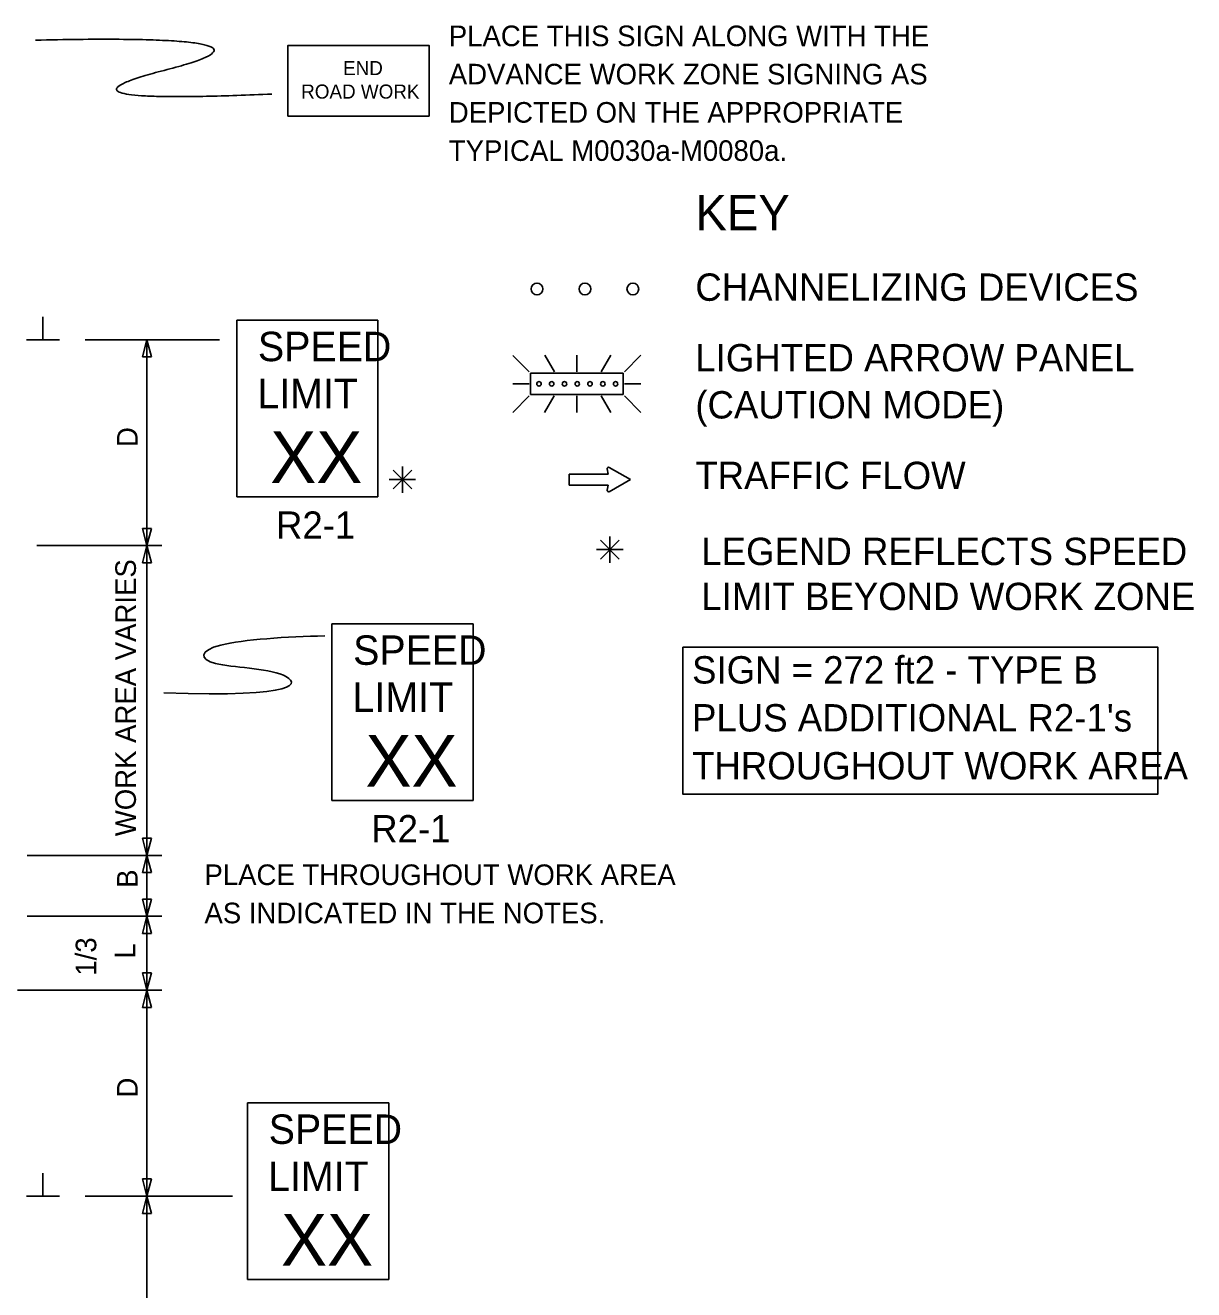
# Model space of a CAD drawing. Extents: x 16741 to 18479, y 6916 to 8211.
# Drawn here: x 17027.6 to 17424.7, y 7781.4 to 8211.2 of the extents above; entities that cross this region are included whole.
import ezdxf

# ---------------------------------------------------------------- set-up
doc = ezdxf.new("R2010")
doc.units = 0
for name, color, linetype in [('MT_SCRATCH_LEVEL_E', 7, 'Continuous'), ('PAVT_EDGE_EX', 7, 'Continuous'), ('TRAFFIC_SIGNS_PR', 7, 'Continuous'), ('TYPICAL_TEXT_DIMEN_EX', 7, 'Continuous'), ('TYPICAL_TEXT_DIMEN_PR', 7, 'Continuous')]:
    doc.layers.add(name, color=color, linetype=linetype)

msp = doc.modelspace()

# ---------------------------------------------------------------- linework, layer by layer
at = {"layer": 'MT_SCRATCH_LEVEL_E'}
for p, q in [((17225.35, 8060.43), (17225.67, 8058.65)), ((17225.35, 8060.43), (17225.67, 8058.65)), ((17233.28, 8056.8), (17226.04, 8060.91)), ((17233.28, 8056.8), (17226.04, 8060.91)), ((17225.67, 8058.65), (17212.41, 8058.65)), ((17212.41, 8058.65), (17212.41, 8054.91)), ((17225.67, 8058.65), (17212.41, 8058.65)), ((17212.41, 8058.65), (17212.41, 8054.91)), ((17212.41, 8054.91), (17225.67, 8054.91)), ((17212.41, 8054.91), (17225.67, 8054.91)), ((17225.67, 8054.91), (17225.35, 8053.13)), ((17225.67, 8054.91), (17225.35, 8053.13)), ((17226.04, 8052.65), (17233.28, 8056.8)), ((17226.04, 8052.65), (17233.28, 8056.8))]:
    msp.add_line(p, q, dxfattribs=at)
for centre, start, end in [((17225.81, 8060.5), 60.4248, 189.9638), ((17225.81, 8060.5), 60.4248, 189.9638), ((17225.81, 8053.06), 170.0362, 299.7731), ((17225.81, 8053.06), 170.0362, 299.7731)]:
    msp.add_arc(centre, 0.463, start, end, dxfattribs=at)
at = {"layer": 'PAVT_EDGE_EX'}
msp.add_line((17028.22, 7883.18), (17024.92, 7883.18), dxfattribs=at)
at = {"layer": 'TRAFFIC_SIGNS_PR'}
for p, q in [((17099.42, 8110.93), (17147.42, 8110.93)), ((17099.42, 8050.93), (17099.42, 8110.93)), ((17147.42, 8050.93), (17147.42, 8110.93)), ((17193.23, 8098.99), (17198.86, 8093.36)), ((17207.4, 8093.36), (17204.15, 8099)), ((17215.03, 8093.36), (17215.03, 8099)), ((17223.3, 8093.36), (17226.56, 8099)), ((17231.2, 8093.36), (17236.85, 8099)), ((17198.86, 8089.29), (17193.23, 8089.29)), ((17202.14, 8089.29), (17202.14, 8089.29)), ((17206.49, 8089.29), (17206.49, 8089.29)), ((17210.83, 8089.29), (17210.83, 8089.29)), ((17215.18, 8089.29), (17215.18, 8089.29)), ((17219.53, 8089.29), (17219.53, 8089.29)), ((17223.88, 8089.29), (17223.88, 8089.29)), ((17228.22, 8089.29), (17228.22, 8089.29)), ((17231.2, 8089.29), (17236.85, 8089.29)), ((17193.23, 8079.59), (17198.86, 8085.23)), ((17204.1, 8079.59), (17207.35, 8085.23)), ((17215.03, 8085.23), (17215.03, 8079.59)), ((17226.61, 8079.59), (17223.35, 8085.23)), ((17231.2, 8085.23), (17236.85, 8079.59)), ((17099.42, 8050.93), (17147.42, 8050.93)), ((17131.79, 8007.71), (17179.79, 8007.71)), ((17131.79, 7947.71), (17131.79, 8007.71)), ((17179.79, 7947.71), (17179.79, 8007.71)), ((17131.79, 7947.71), (17179.79, 7947.71)), ((17103.1, 7844.86), (17151.1, 7844.86)), ((17103.1, 7784.86), (17103.1, 7844.86)), ((17151.1, 7784.86), (17151.1, 7844.86)), ((17103.1, 7784.86), (17151.1, 7784.86))]:
    msp.add_line(p, q, dxfattribs=at)
for points in [[(17116.83, 8180.34), (17164.83, 8180.34), (17164.83, 8204.34), (17116.83, 8204.34)], [(17230.74, 8085.69), (17199.33, 8085.69), (17199.33, 8092.89), (17230.74, 8092.89)]]:
    msp.add_lwpolyline(points, close=True, dxfattribs=at)
for centre, radius in [((17201.49, 8121.55), 2), ((17217.79, 8121.55), 2), ((17234.09, 8121.55), 2), ((17202.18, 8089.29), 0.758), ((17206.49, 8089.29), 0.758), ((17210.83, 8089.29), 0.758), ((17215.18, 8089.29), 0.758), ((17219.53, 8089.29), 0.758), ((17223.87, 8089.29), 0.758), ((17228.22, 8089.29), 0.758)]:
    msp.add_circle(centre, radius, dxfattribs=at)
msp.add_open_spline([(17111.38, 8187.83), (17028.46, 8184.05), (17122.92, 8208.18), (17031.07, 8206.15)], degree=2, dxfattribs=at)
at = {"layer": 'TYPICAL_TEXT_DIMEN_EX'}
msp.add_lwpolyline([(17251.08, 7999.84), (17412.49, 7999.84), (17412.49, 7949.77), (17251.08, 7949.77)], close=True, dxfattribs=at)
at = {"layer": 'TYPICAL_TEXT_DIMEN_PR'}
for p, q in [((17033.54, 8104.3), (17033.54, 8112.08)), ((17033.54, 8104.3), (17027.92, 8104.3)), ((17039.17, 8104.3), (17033.54, 8104.3)), ((17047.92, 8104.31), (17093.55, 8104.31)), ((17067.35, 8098.45), (17068.92, 8104.31)), ((17068.92, 8104.31), (17068.92, 8034.31)), ((17068.92, 8104.31), (17070.49, 8098.45)), ((17068.92, 8098.45), (17067.35, 8098.45)), ((17070.49, 8098.45), (17068.92, 8098.45)), ((17152.57, 8059.95), (17158.94, 8053.57)), ((17158.94, 8059.95), (17152.57, 8053.57)), ((17155.76, 8056.76), (17155.76, 8061.22)), ((17155.76, 8056.76), (17151.22, 8056.76)), ((17155.76, 8056.76), (17158.94, 8056.76)), ((17155.76, 8056.76), (17160.23, 8056.76)), ((17155.76, 8056.76), (17155.76, 8052.26)), ((17068.92, 8034.31), (17067.35, 8040.17)), ((17067.35, 8040.17), (17068.92, 8040.17)), ((17068.92, 8040.17), (17070.49, 8040.17)), ((17070.49, 8040.17), (17068.92, 8034.31)), ((17031.53, 8034.31), (17073.92, 8034.31)), ((17067.35, 8028.45), (17068.92, 8034.31)), ((17068.92, 8034.31), (17068.92, 7929.01)), ((17068.92, 8034.31), (17070.49, 8028.45)), ((17223.1, 8036.14), (17229.48, 8029.76)), ((17229.48, 8036.14), (17223.1, 8029.76)), ((17226.29, 8032.95), (17226.29, 8037.4)), ((17226.29, 8032.95), (17221.76, 8032.95)), ((17226.29, 8032.95), (17229.48, 8032.95)), ((17226.29, 8032.95), (17230.77, 8032.95)), ((17226.29, 8032.95), (17226.29, 8028.45)), ((17068.92, 8028.45), (17067.35, 8028.45)), ((17070.49, 8028.45), (17068.92, 8028.45)), ((17068.92, 7929.01), (17067.35, 7934.87)), ((17067.35, 7934.87), (17068.92, 7934.87)), ((17068.92, 7934.87), (17070.49, 7934.87)), ((17070.49, 7934.87), (17068.92, 7929.01)), ((17028.22, 7929.01), (17073.92, 7929.01)), ((17067.35, 7923.15), (17068.92, 7929.01)), ((17068.92, 7929.01), (17068.92, 7908.31)), ((17068.92, 7929.01), (17070.49, 7923.15)), ((17068.92, 7923.15), (17067.35, 7923.15)), ((17070.49, 7923.15), (17068.92, 7923.15)), ((17068.92, 7908.31), (17067.35, 7914.17)), ((17067.35, 7914.17), (17068.92, 7914.17)), ((17068.92, 7914.17), (17070.49, 7914.17)), ((17070.49, 7914.17), (17068.92, 7908.31)), ((17028.22, 7908.31), (17069.78, 7908.31)), ((17067.35, 7902.44), (17068.92, 7908.31)), ((17068.92, 7908.31), (17068.92, 7883.18)), ((17068.92, 7908.31), (17070.49, 7902.44)), ((17069.78, 7908.31), (17073.92, 7908.31)), ((17068.92, 7902.44), (17067.35, 7902.44)), ((17070.49, 7902.44), (17068.92, 7902.44)), ((17068.92, 7883.18), (17067.35, 7889.04)), ((17067.35, 7889.04), (17068.92, 7889.04)), ((17068.92, 7889.04), (17070.49, 7889.04)), ((17070.49, 7889.04), (17068.92, 7883.18)), ((17028.22, 7883.18), (17073.92, 7883.18)), ((17067.35, 7877.32), (17068.92, 7883.18)), ((17068.92, 7883.18), (17068.92, 7813.18)), ((17068.92, 7883.18), (17070.49, 7877.32)), ((17068.92, 7877.32), (17067.35, 7877.32)), ((17070.49, 7877.32), (17068.92, 7877.32)), ((17033.54, 7813.18), (17033.54, 7820.97)), ((17068.92, 7813.18), (17067.35, 7819.04)), ((17067.35, 7819.04), (17068.92, 7819.04)), ((17068.92, 7819.04), (17070.49, 7819.04)), ((17070.49, 7819.04), (17068.92, 7813.18)), ((17033.54, 7813.18), (17027.92, 7813.18)), ((17039.17, 7813.18), (17033.54, 7813.18)), ((17047.92, 7813.18), (17097.97, 7813.18)), ((17067.35, 7807.32), (17068.92, 7813.18)), ((17068.92, 7813.18), (17068.92, 7743.18)), ((17068.92, 7813.18), (17070.49, 7807.32)), ((17068.92, 7807.32), (17067.35, 7807.32)), ((17070.49, 7807.32), (17068.92, 7807.32))]:
    msp.add_line(p, q, dxfattribs=at)
msp.add_open_spline([(17074.68, 7984.23), (17121.44, 7982.57), (17120.86, 7992.78), (17086.54, 7992.78), (17086.54, 8001.5), (17116.52, 8003.35), (17129.34, 8003.62)], degree=3, dxfattribs=at)

# ---------------------------------------------------------------- texts
at = {"layer": 'TRAFFIC_SIGNS_PR'}
for s, height, p in [('PLACE THIS SIGN ALONG WITH THE', 7, (17171.52, 8204.09)), ('END', 4.789, (17135.58, 8194.25)), ('ADVANCE WORK ZONE SIGNING AS', 7, (17171.52, 8191.09)), ('ROAD WORK', 4.789, (17121.34, 8186.27)), ('DEPICTED ON THE APPROPRIATE', 7, (17171.52, 8178.09)), ('TYPICAL M0030a-M0080a.', 7, (17171.52, 8165.09)), ('SPEED', 10, (17106.63, 8097.01)), ('LIMIT', 10, (17106.43, 8081.01)), ('XX', 17.538, (17110.82, 8055.63)), ('R2-1', 9.3, (17112.77, 8036.63)), ('SPEED', 10, (17139, 7993.79)), ('LIMIT', 10, (17138.8, 7977.79)), ('XX', 17.538, (17143.19, 7952.41)), ('R2-1', 9.3, (17145.14, 7933.42)), ('PLACE THROUGHOUT WORK AREA', 7, (17088.46, 7918.93)), ('AS INDICATED IN THE NOTES.', 7, (17088.46, 7905.93)), ('SPEED', 10, (17110.3, 7830.94)), ('LIMIT', 10, (17110.1, 7814.94)), ('XX', 17.538, (17114.49, 7789.56))]:
    msp.add_text(s, height=height, dxfattribs=at).set_placement(p)
at = {"layer": 'TYPICAL_TEXT_DIMEN_EX'}
for s, height, p in [('KEY', 12, (17255.33, 8141.53)), ('CHANNELIZING DEVICES', 9.3, (17255.33, 8117.53)), ('LIGHTED ARROW PANEL', 9.3, (17255.33, 8093.53)), ('(CAUTION MODE)', 9.3, (17255.33, 8077.53)), ('TRAFFIC FLOW', 9.3, (17255.33, 8053.53)), ('LEGEND REFLECTS SPEED', 9.3, (17257.37, 8027.69)), ('LIMIT BEYOND WORK ZONE', 9.3, (17257.37, 8012.39)), ('SIGN = 272 ft2 - TYPE B', 9.3, (17254.21, 7987.43)), ("PLUS ADDITIONAL R2-1's", 9.3, (17254.21, 7971.13)), ('THROUGHOUT WORK AREA', 9.3, (17254.21, 7954.83))]:
    msp.add_text(s, height=height, dxfattribs=at).set_placement(p)
at = {"layer": 'TYPICAL_TEXT_DIMEN_PR'}
for s, p in [('D', (17065.73, 8067.83)), ('WORK AREA VARIES', (17065.16, 7935.53)), ('B', (17065.73, 7918)), ('1/3', (17051.68, 7888.13)), ('L', (17064.98, 7893.92)), ('D', (17065.73, 7846.71))]:
    msp.add_text(s, height=7, rotation=90, dxfattribs=at).set_placement(p)

doc.saveas('drawing.dxf')
